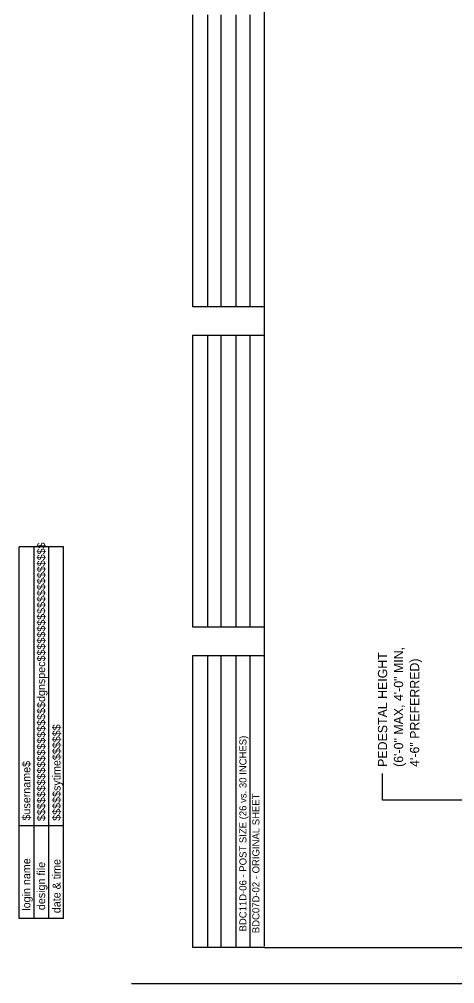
# Model space of a CAD drawing. Extents: x -17866409 to 26050223, y -3454119 to 12035012.
# Drawn here: x -3.03 to 8.75, y 0 to 26.09 of the extents above; entities that cross this region are included whole.
import ezdxf

# ---------------------------------------------------------------- set-up
doc = ezdxf.new("R2010")
doc.units = 0
doc.layers.add('1', color=7, linetype='Continuous')
doc.layers.add('2', color=7, linetype='Continuous')

msp = doc.modelspace()

# ---------------------------------------------------------------- linework, layer by layer
at = {"layer": '1'}
for p, q in [((3.6, 1.017), (3.6, 42.342)), ((1.667, 18.317), (1.667, 26.217)), ((2.067, 18.317), (2.067, 26.217)), ((2.433, 18.317), (2.433, 26.217)), ((2.833, 18.317), (2.833, 26.217)), ((3.217, 18.317), (3.217, 26.217)), ((3.6, 18.317), (1.667, 18.317)), ((1.667, 9.65), (1.667, 17.55)), ((1.667, 17.55), (3.6, 17.55)), ((2.067, 9.65), (2.067, 17.55)), ((2.433, 9.65), (2.433, 17.55)), ((2.833, 9.65), (2.833, 17.55)), ((3.217, 9.65), (3.217, 17.55)), ((-3.033, 1.767), (-3.033, 11.825)), ((-1.833, 11.825), (-3.033, 11.825)), ((-2.633, 1.767), (-2.633, 11.825)), ((-2.233, 1.767), (-2.233, 11.825)), ((-1.833, 1.767), (-1.833, 11.825)), ((3.6, 9.65), (1.667, 9.65)), ((1.667, 0.983), (1.667, 8.883)), ((1.667, 8.883), (3.6, 8.883)), ((2.067, 0.983), (2.067, 8.883)), ((2.433, 0.983), (2.433, 8.883)), ((2.833, 0.983), (2.833, 8.883)), ((3.217, 0.983), (3.217, 8.883)), ((6.799, 4.967), (6.799, 5.692)), ((10.374, 4.967), (6.799, 4.967)), ((-1.833, 4.275), (-3.033, 4.275)), ((-1.833, 1.767), (-3.033, 1.767)), ((3.6, 0.983), (1.667, 0.983)), ((3.6, 0.983), (68.183, 0.983)), ((68.892, 0), (0, 0))]:
    msp.add_line(p, q, dxfattribs=at)

# ---------------------------------------------------------------- texts
for s, height, p in [('$$$$$$$$$$$$$$$$$$$$dgnspec$$$$$$$$$$$$$$$$$$$$', 0.21665, (-2.333, 4.4)), ('$$$$$sytime$$$$$$', 0.21665, (-1.917, 4.408)), ('BDC11D-06 - POST SIZE (26 vs. 30 INCHES)', 0.19265, (3.116, 1.413)), ('$username$', 0.2167, (-2.733, 4.417)), ('BDC07D-02 - ORIGINAL SHEET', 0.19265, (3.467, 1.367)), ('login name', 0.2167, (-2.733, 1.975)), ('design file', 0.21665, (-2.333, 1.992)), ('date & time', 0.21665, (-1.917, 1.908))]:
    msp.add_text(s, height=height, rotation=90, dxfattribs=at).set_placement(p)
at = {"layer": '2'}
for s, p in [('PEDESTAL HEIGHT', (6.924, 5.867)), ('(6\'-0" MAX, 4\'-0" MIN,', (7.357, 5.867)), ('4\'-6" PREFERRED)', (7.791, 5.867))]:
    msp.add_text(s, height=0.25, rotation=90, dxfattribs=at).set_placement(p)

doc.saveas('drawing.dxf')
